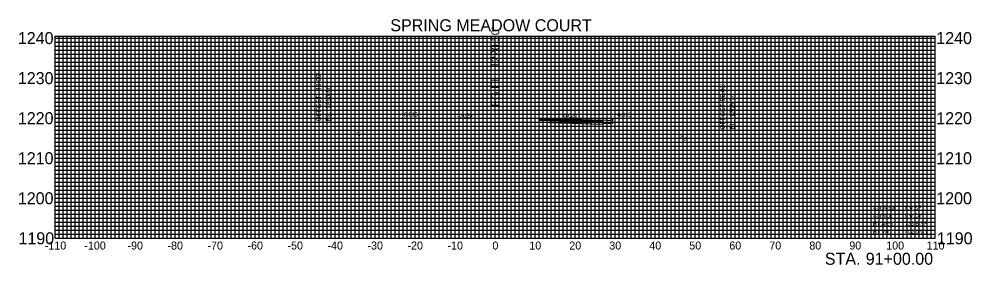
# Model space of a CAD drawing. Extents: x -119 to 119, y 1183 to 1245.
import ezdxf

# ---------------------------------------------------------------- set-up
doc = ezdxf.new("R2010")
doc.units = 0
for name, color, linetype in [('DES - SHEET - Light Grid', 7, 'Continuous'), ('DES - SHEET - Linework', 7, 'Continuous'), ('DES - XS - Proposed - Finished Grade Slopes Text', 7, 'Continuous'), ('DES - XS - Proposed - Text', 7, 'Continuous'), ('SUR - DTM - Breaklines', 7, 'Continuous'), ('SUR - DTM - Graphic Voids', 7, 'Continuous')]:
    doc.layers.add(name, color=color, linetype=linetype)

msp = doc.modelspace()

# ---------------------------------------------------------------- linework, layer by layer
at = {"layer": 'DES - SHEET - Light Grid'}
for p, q in [((-110, 1239), (110, 1239)), ((-109, 1190), (-109, 1240.5)), ((-108, 1190), (-108, 1240.5)), ((-107, 1190), (-107, 1240.5)), ((-106, 1190), (-106, 1240.5)), ((-105, 1190), (-105, 1240.5)), ((-104, 1190), (-104, 1240.5)), ((-103, 1190), (-103, 1240.5)), ((-102, 1190), (-102, 1240.5)), ((-101, 1190), (-101, 1240.5)), ((-99, 1190), (-99, 1240.5)), ((-98, 1190), (-98, 1240.5)), ((-97, 1190), (-97, 1240.5)), ((-96, 1190), (-96, 1240.5)), ((-95, 1190), (-95, 1240.5)), ((-94, 1190), (-94, 1240.5)), ((-93, 1190), (-93, 1240.5)), ((-92, 1190), (-92, 1240.5)), ((-91, 1190), (-91, 1240.5)), ((-89, 1190), (-89, 1240.5)), ((-88, 1190), (-88, 1240.5)), ((-87, 1190), (-87, 1240.5)), ((-86, 1190), (-86, 1240.5)), ((-85, 1190), (-85, 1240.5)), ((-84, 1190), (-84, 1240.5)), ((-83, 1190), (-83, 1240.5)), ((-82, 1190), (-82, 1240.5)), ((-81, 1190), (-81, 1240.5)), ((-79, 1190), (-79, 1240.5)), ((-78, 1190), (-78, 1240.5)), ((-77, 1190), (-77, 1240.5)), ((-76, 1190), (-76, 1240.5)), ((-75, 1190), (-75, 1240.5)), ((-74, 1190), (-74, 1240.5)), ((-73, 1190), (-73, 1240.5)), ((-72, 1190), (-72, 1240.5)), ((-71, 1190), (-71, 1240.5)), ((-69, 1190), (-69, 1240.5)), ((-68, 1190), (-68, 1240.5)), ((-67, 1190), (-67, 1240.5)), ((-66, 1190), (-66, 1240.5)), ((-65, 1190), (-65, 1240.5)), ((-64, 1190), (-64, 1240.5)), ((-63, 1190), (-63, 1240.5)), ((-62, 1190), (-62, 1240.5)), ((-61, 1190), (-61, 1240.5)), ((-59, 1190), (-59, 1240.5)), ((-58, 1190), (-58, 1240.5)), ((-57, 1190), (-57, 1240.5)), ((-56, 1190), (-56, 1240.5)), ((-55, 1190), (-55, 1240.5)), ((-54, 1190), (-54, 1240.5)), ((-53, 1190), (-53, 1240.5)), ((-52, 1190), (-52, 1240.5)), ((-51, 1190), (-51, 1240.5)), ((-49, 1190), (-49, 1240.5)), ((-48, 1190), (-48, 1240.5)), ((-47, 1190), (-47, 1240.5)), ((-46, 1190), (-46, 1240.5)), ((-45, 1190), (-45, 1240.5)), ((-44, 1190), (-44, 1240.5)), ((-43, 1190), (-43, 1240.5)), ((-42, 1190), (-42, 1240.5)), ((-41, 1190), (-41, 1240.5)), ((-39, 1190), (-39, 1240.5)), ((-38, 1190), (-38, 1240.5)), ((-37, 1190), (-37, 1240.5)), ((-36, 1190), (-36, 1240.5)), ((-35, 1190), (-35, 1240.5)), ((-34, 1190), (-34, 1240.5)), ((-33, 1190), (-33, 1240.5)), ((-32, 1190), (-32, 1240.5)), ((-31, 1190), (-31, 1240.5)), ((-29, 1190), (-29, 1240.5)), ((-28, 1190), (-28, 1240.5)), ((-27, 1190), (-27, 1240.5)), ((-26, 1190), (-26, 1240.5)), ((-25, 1190), (-25, 1240.5)), ((-24, 1190), (-24, 1240.5)), ((-23, 1190), (-23, 1240.5)), ((-22, 1190), (-22, 1240.5)), ((-21, 1190), (-21, 1240.5)), ((-19, 1190), (-19, 1240.5)), ((-18, 1190), (-18, 1240.5)), ((-17, 1190), (-17, 1240.5)), ((-16, 1190), (-16, 1240.5)), ((-15, 1190), (-15, 1240.5)), ((-14, 1190), (-14, 1240.5)), ((-13, 1190), (-13, 1240.5)), ((-12, 1190), (-12, 1240.5)), ((-11, 1190), (-11, 1240.5)), ((-9, 1190), (-9, 1240.5)), ((-8, 1190), (-8, 1240.5)), ((-7, 1190), (-7, 1240.5)), ((-6, 1190), (-6, 1240.5)), ((-5, 1190), (-5, 1240.5)), ((-4, 1190), (-4, 1240.5)), ((-3, 1190), (-3, 1240.5)), ((-2, 1190), (-2, 1240.5)), ((-1, 1190), (-1, 1240.5)), ((1, 1190), (1, 1240.5)), ((2, 1190), (2, 1240.5)), ((3, 1190), (3, 1240.5)), ((4, 1190), (4, 1240.5)), ((5, 1190), (5, 1240.5)), ((6, 1190), (6, 1240.5)), ((7, 1190), (7, 1240.5)), ((8, 1190), (8, 1240.5)), ((9, 1190), (9, 1240.5)), ((11, 1190), (11, 1240.5)), ((12, 1190), (12, 1240.5)), ((13, 1190), (13, 1240.5)), ((14, 1190), (14, 1240.5)), ((15, 1190), (15, 1240.5)), ((16, 1190), (16, 1240.5)), ((17, 1190), (17, 1240.5)), ((18, 1190), (18, 1240.5)), ((19, 1190), (19, 1240.5)), ((21, 1190), (21, 1240.5)), ((22, 1190), (22, 1240.5)), ((23, 1190), (23, 1240.5)), ((24, 1190), (24, 1240.5)), ((25, 1190), (25, 1240.5)), ((26, 1190), (26, 1240.5)), ((27, 1190), (27, 1240.5)), ((28, 1190), (28, 1240.5)), ((29, 1190), (29, 1240.5)), ((31, 1190), (31, 1240.5)), ((32, 1190), (32, 1240.5)), ((33, 1190), (33, 1240.5)), ((34, 1190), (34, 1240.5)), ((35, 1190), (35, 1240.5)), ((36, 1190), (36, 1240.5)), ((37, 1190), (37, 1240.5)), ((38, 1190), (38, 1240.5)), ((39, 1190), (39, 1240.5)), ((41, 1190), (41, 1240.5)), ((42, 1190), (42, 1240.5)), ((43, 1190), (43, 1240.5)), ((44, 1190), (44, 1240.5)), ((45, 1190), (45, 1240.5)), ((46, 1190), (46, 1240.5)), ((47, 1190), (47, 1240.5)), ((48, 1190), (48, 1240.5)), ((49, 1190), (49, 1240.5)), ((51, 1190), (51, 1240.5)), ((52, 1190), (52, 1240.5)), ((53, 1190), (53, 1240.5)), ((54, 1190), (54, 1240.5)), ((55, 1190), (55, 1240.5)), ((56, 1190), (56, 1240.5)), ((57, 1190), (57, 1240.5)), ((58, 1190), (58, 1240.5)), ((59, 1190), (59, 1240.5)), ((61, 1190), (61, 1240.5)), ((62, 1190), (62, 1240.5)), ((63, 1190), (63, 1240.5)), ((64, 1190), (64, 1240.5)), ((65, 1190), (65, 1240.5)), ((66, 1190), (66, 1240.5)), ((67, 1190), (67, 1240.5)), ((68, 1190), (68, 1240.5)), ((69, 1190), (69, 1240.5)), ((71, 1190), (71, 1240.5)), ((72, 1190), (72, 1240.5)), ((73, 1190), (73, 1240.5)), ((74, 1190), (74, 1240.5)), ((75, 1190), (75, 1240.5)), ((76, 1190), (76, 1240.5)), ((77, 1190), (77, 1240.5)), ((78, 1190), (78, 1240.5)), ((79, 1190), (79, 1240.5)), ((81, 1190), (81, 1240.5)), ((82, 1190), (82, 1240.5)), ((83, 1190), (83, 1240.5)), ((84, 1190), (84, 1240.5)), ((85, 1190), (85, 1240.5)), ((86, 1190), (86, 1240.5)), ((87, 1190), (87, 1240.5)), ((88, 1190), (88, 1240.5)), ((89, 1190), (89, 1240.5)), ((91, 1190), (91, 1240.5)), ((92, 1190), (92, 1240.5)), ((93, 1190), (93, 1240.5)), ((94, 1190), (94, 1240.5)), ((95, 1190), (95, 1240.5)), ((96, 1190), (96, 1240.5)), ((97, 1190), (97, 1240.5)), ((98, 1190), (98, 1240.5)), ((99, 1190), (99, 1240.5)), ((101, 1190), (101, 1240.5)), ((102, 1190), (102, 1240.5)), ((103, 1190), (103, 1240.5)), ((104, 1190), (104, 1240.5)), ((105, 1190), (105, 1240.5)), ((106, 1190), (106, 1240.5)), ((107, 1190), (107, 1240.5)), ((108, 1190), (108, 1240.5)), ((109, 1190), (109, 1240.5)), ((-110, 1238), (110, 1238)), ((-110, 1237), (110, 1237)), ((-110, 1236), (110, 1236)), ((-110, 1235), (110, 1235)), ((-110, 1234), (110, 1234)), ((-110, 1233), (110, 1233)), ((-110, 1232), (110, 1232)), ((-110, 1231), (110, 1231)), ((-110, 1229), (110, 1229)), ((-110, 1228), (110, 1228)), ((-110, 1227), (110, 1227)), ((-110, 1226), (110, 1226)), ((-110, 1225), (110, 1225)), ((-110, 1224), (110, 1224)), ((-110, 1223), (110, 1223)), ((-110, 1222), (110, 1222)), ((-110, 1221), (110, 1221)), ((-110, 1219), (110, 1219)), ((-110, 1218), (110, 1218)), ((-110, 1217), (110, 1217)), ((-110, 1216), (110, 1216)), ((-110, 1215), (110, 1215)), ((-110, 1214), (110, 1214)), ((-110, 1213), (110, 1213)), ((-110, 1212), (110, 1212)), ((-110, 1211), (110, 1211)), ((-110, 1209), (110, 1209)), ((-110, 1208), (110, 1208)), ((-110, 1207), (110, 1207)), ((-110, 1206), (110, 1206)), ((-110, 1205), (110, 1205)), ((-110, 1204), (110, 1204)), ((-110, 1203), (110, 1203)), ((-110, 1202), (110, 1202)), ((-110, 1201), (110, 1201)), ((-110, 1199), (110, 1199)), ((-110, 1198), (110, 1198)), ((-110, 1197), (110, 1197)), ((-110, 1196), (110, 1196)), ((-110, 1195), (110, 1195)), ((-110, 1194), (110, 1194)), ((-110, 1193), (110, 1193)), ((-110, 1192), (110, 1192)), ((-110, 1191), (110, 1191))]:
    msp.add_line(p, q, dxfattribs=at)
at = {"layer": 'DES - SHEET - Linework'}
for p, q in [((-110, 1240.5), (110, 1240.5)), ((-110, 1190), (-110, 1240.5)), ((-110, 1240), (110, 1240)), ((-100, 1190), (-100, 1240.5)), ((-90, 1190), (-90, 1240.5)), ((-80, 1190), (-80, 1240.5)), ((-70, 1190), (-70, 1240.5)), ((-60, 1190), (-60, 1240.5)), ((-50, 1190), (-50, 1240.5)), ((-40, 1190), (-40, 1240.5)), ((-30, 1190), (-30, 1240.5)), ((-20, 1190), (-20, 1240.5)), ((-10, 1190), (-10, 1240.5)), ((0, 1190), (0, 1240.5)), ((10, 1190), (10, 1240.5)), ((20, 1190), (20, 1240.5)), ((30, 1190), (30, 1240.5)), ((40, 1190), (40, 1240.5)), ((50, 1190), (50, 1240.5)), ((60, 1190), (60, 1240.5)), ((70, 1190), (70, 1240.5)), ((80, 1190), (80, 1240.5)), ((90, 1190), (90, 1240.5)), ((100, 1190), (100, 1240.5)), ((110, 1190), (110, 1240.5)), ((-110, 1230), (110, 1230)), ((-110, 1220), (110, 1220)), ((-110, 1210), (110, 1210)), ((-110, 1200), (110, 1200)), ((-110, 1190), (110, 1190))]:
    msp.add_line(p, q, dxfattribs=at)
at = {"layer": 'SUR - DTM - Breaklines'}
for p, q in [((10.8, 1219.94), (26.85, 1219.43)), ((10.8, 1219.77), (26.85, 1219.26)), ((10.81, 1220.04), (26.85, 1219.53)), ((10.78, 1219.02), (26.83, 1218.51)), ((10.79, 1219.52), (26.84, 1219.01)), ((26.84, 1219.01), (26.83, 1218.51)), ((26.85, 1219.26), (26.84, 1219.01)), ((26.85, 1219.53), (26.85, 1219.43)), ((26.85, 1219.43), (26.85, 1219.26))]:
    msp.add_line(p, q, dxfattribs=at)
msp.add_lwpolyline([(29.36, 1219.87), (28.86, 1219.84), (28.82, 1219.37), (26.85, 1219.53), (26.85, 1218.78), (29.36, 1218.73)], close=True, dxfattribs=at)
at = {"layer": 'SUR - DTM - Graphic Voids'}
msp.add_line((35.27, 1219.96), (29.36, 1219.87), dxfattribs=at)

# ---------------------------------------------------------------- texts
at = {"layer": 'DES - XS - Proposed - Finished Grade Slopes Text'}
for s, height, rotation, p in [("-43.00'", 1.2, 90, (-43.6, 1226.25)), ('1210.80', 1.2, 90, (-41.2, 1222.18)), ("58.01'", 1.2, 90, (57.41, 1224.19)), ('OFFSET ', 1.2, 90, (-43.6, 1219.2)), ('1208.74', 1.2, 90, (59.81, 1220.13)), ('OFFSET ', 1.2, 90, (57.41, 1217.14)), ('EL. ', 1.2, 90, (-41.2, 1219.2)), ('0.015', 1, 359.077, (-22.81, 1220.47)), ('-0.020', 1, 1.1047, (-9.61, 1220.11)), ('0.020', 1, 358.8953, (17.06, 1220.18)), ('0.015', 1, 0.8411, (30.56, 1220.35)), ('EL. ', 1.2, 90, (59.81, 1217.14)), ('2:1', 1, 26.4312, (-34.31, 1215.42)), ('2:1', 1, 333.4225, (45.89, 1215.11))]:
    msp.add_text(s, height=height, rotation=rotation, dxfattribs=at).set_placement(p)
at = {"layer": 'DES - XS - Proposed - Text'}
for s, height, p in [('SPRING MEADOW COURT', 3, (-26.24, 1241.7)), ('1240', 3, (-119.36, 1238.5)), ('1240', 3, (110.24, 1238.5)), ('1230', 3, (-119.36, 1228.5)), ('1230', 3, (110.24, 1228.5)), ('1220', 3, (-119.36, 1218.5)), ('1220', 3, (110.24, 1218.5)), ('1210', 3, (-119.36, 1208.5)), ('1210', 3, (110.24, 1208.5)), ('1200', 3, (-119.36, 1198.5)), ('1200', 3, (110.24, 1198.5)), ('Cut Area', 1, (94.4, 1197.2)), ('Cut Area', 1, (94.4, 1197.2)), ('Cut Vol.', 1, (94.4, 1195.2)), ('Cut Vol.', 1, (94.4, 1195.2)), ('0.0', 1, (102.4, 1197.2)), ('0.0', 1, (102.4, 1197.2)), ('0.0', 1, (102.4, 1195.2)), ('0.0', 1, (102.4, 1195.2)), (' SF', 1, (104.34, 1197.2)), (' SF', 1, (104.34, 1197.2)), (' CY', 1, (104.34, 1195.2)), (' CY', 1, (104.34, 1195.2)), ('Fill Area', 1, (94.4, 1193.2)), ('Fill Area', 1, (94.4, 1193.2)), ('733.8', 1, (102.4, 1193.2)), ('733.8', 1, (102.4, 1193.2)), (' SF', 1, (105.89, 1193.2)), (' SF', 1, (105.89, 1193.2)), ('1190', 3, (-119.2, 1188.5)), ('Fill Vol.', 1, (94.4, 1191.2)), ('Fill Vol.', 1, (94.4, 1191.2)), ('402.0', 1, (102.4, 1191.2)), ('402.0', 1, (102.4, 1191.2)), (' CY', 1, (105.89, 1191.2)), (' CY', 1, (105.89, 1191.2)), ('1190', 3, (110.4, 1188.5)), ('-110', 2, (-112.62, 1187.2)), ('-100', 2, (-102.73, 1187.2)), ('-90', 2, (-91.95, 1187.2)), ('-80', 2, (-81.95, 1187.2)), ('-70', 2, (-71.95, 1187.2)), ('-60', 2, (-61.95, 1187.2)), ('-50', 2, (-51.95, 1187.2)), ('-40', 2, (-41.95, 1187.2)), ('-30', 2, (-31.95, 1187.2)), ('-20', 2, (-21.95, 1187.2)), ('-10', 2, (-11.95, 1187.2)), ('0', 2, (-0.71, 1187.2)), ('10', 2, (8.51, 1187.2)), ('20', 2, (18.51, 1187.2)), ('30', 2, (28.51, 1187.2)), ('40', 2, (38.51, 1187.2)), ('50', 2, (48.51, 1187.2)), ('60', 2, (58.51, 1187.2)), ('70', 2, (68.51, 1187.2)), ('80', 2, (78.51, 1187.2)), ('90', 2, (88.51, 1187.2)), ('100', 2, (97.74, 1187.2)), ('110', 2, (107.84, 1187.2)), (' STA. ', 3, (81.28, 1183.4)), ('91+00.00', 3, (92.61, 1183.4))]:
    msp.add_text(s, height=height, dxfattribs=at).set_placement(p)
for s, p in [("1220.50'", (1, 1232.53)), ('FG EL. ', (1, 1222.9))]:
    msp.add_text(s, height=2, rotation=90, dxfattribs=at).set_placement(p)

doc.saveas('drawing.dxf')
